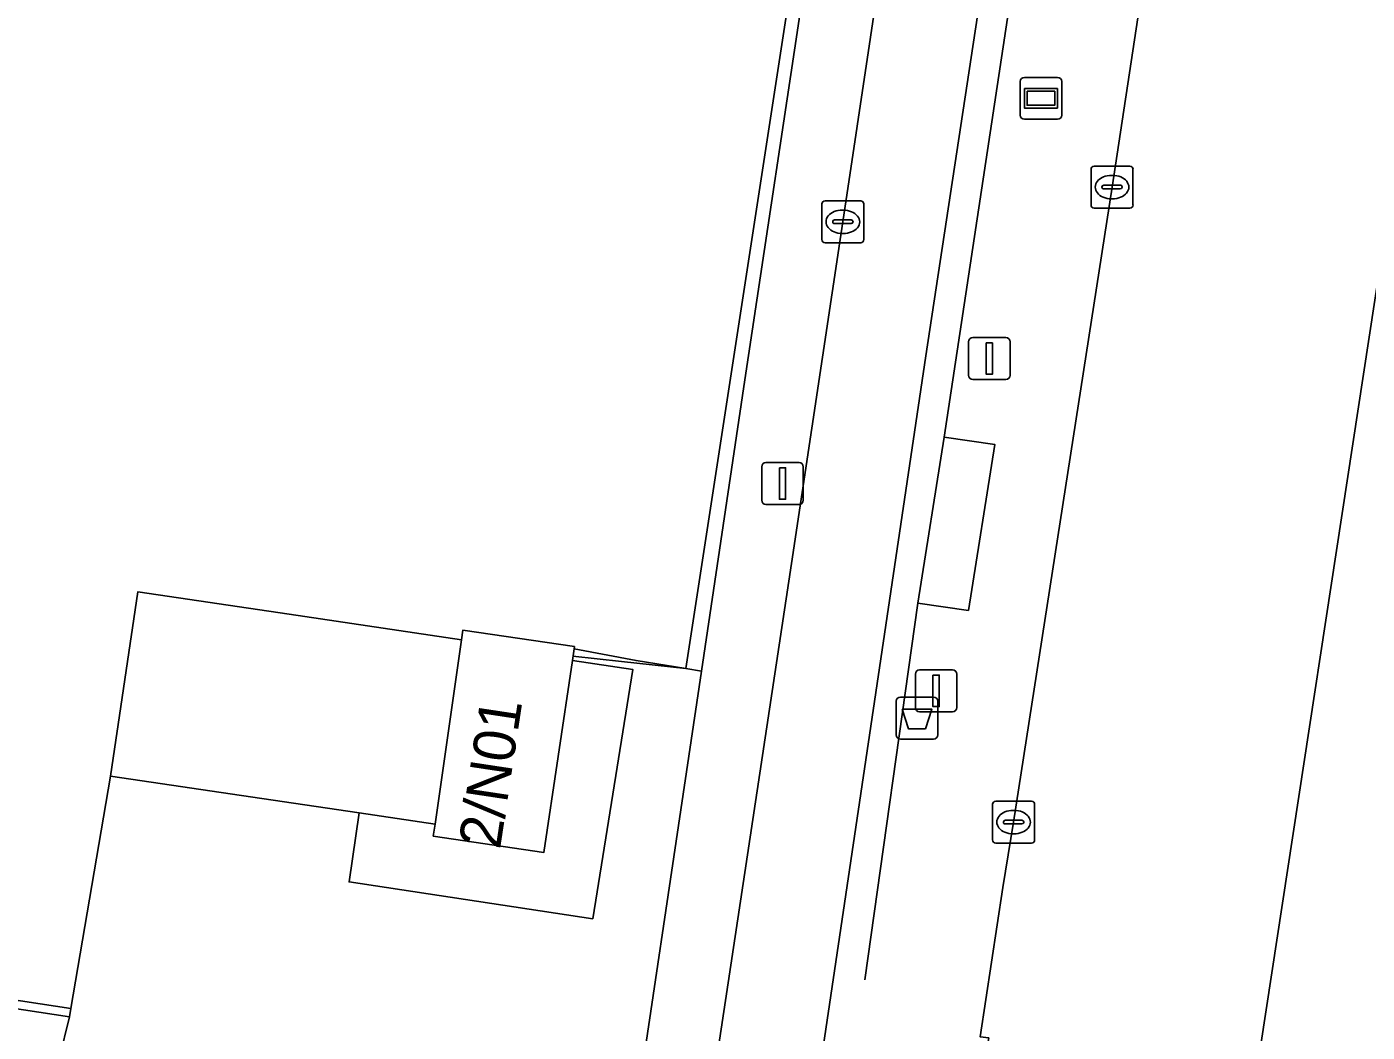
# Model space of a CAD drawing. Extents: x 161090 to 161692, y 379509 to 380907.
# Drawn here: x 161586.23 to 161618.2, y 380444.36 to 380468.34 of the extents above; entities that cross this region are included whole.
import ezdxf

# ---------------------------------------------------------------- set-up
doc = ezdxf.new("R2010")
doc.units = 0
for name, color, linetype in [('IMGEO_Afsluitpaal', 7, 'Continuous'), ('IMGEO_Afvalbak', 7, 'Continuous'), ('IMGEO_Fietspad_gesloten', 7, 'Continuous'), ('IMGEO_Groenvoorziening', 7, 'Continuous'), ('IMGEO_Hek', 7, 'Continuous'), ('IMGEO_Informatiebord', 7, 'Continuous'), ('IMGEO_Kolk', 7, 'Continuous'), ('IMGEO_Lichtmast', 7, 'Continuous'), ('IMGEO_Loofbos', 7, 'Continuous'), ('IMGEO_OVBaan_gesloten', 7, 'Continuous'), ('IMGEO_Pand', 7, 'Continuous'), ('IMGEO_Pand_nummerreeks', 7, 'Continuous'), ('IMGEO_Voetpad_open', 7, 'Continuous')]:
    doc.layers.add(name, color=color, linetype=linetype)

msp = doc.modelspace()

# ---------------------------------------------------------------- linework, layer by layer
at = {"layer": 'IMGEO_Afsluitpaal'}
for p, q in [((161608.694, 380460.028), (161608.694, 380460.828)), ((161608.694, 380460.828), (161608.694, 380460.028)), ((161608.794, 380460.928), (161609.584, 380460.928)), ((161609.584, 380460.928), (161608.794, 380460.928)), ((161609.684, 380460.828), (161609.684, 380460.028)), ((161609.684, 380460.028), (161609.684, 380460.828)), ((161609.584, 380459.928), (161608.794, 380459.928)), ((161608.794, 380459.928), (161609.584, 380459.928)), ((161607.524, 380453.003), (161608.314, 380453.003)), ((161608.314, 380453.003), (161607.524, 380453.003)), ((161607.424, 380452.103), (161607.424, 380452.903)), ((161607.424, 380452.903), (161607.424, 380452.103)), ((161608.414, 380452.903), (161608.414, 380452.103)), ((161608.414, 380452.103), (161608.414, 380452.903)), ((161608.314, 380452.003), (161607.524, 380452.003)), ((161607.524, 380452.003), (161608.314, 380452.003))]:
    msp.add_line(p, q, dxfattribs=at)
for points in [[(161609.114, 380460.803), (161609.264, 380460.803), (161609.264, 380460.053), (161609.114, 380460.053), (161609.114, 380460.803)], [(161607.844, 380452.878), (161607.994, 380452.878), (161607.994, 380452.128), (161607.844, 380452.128), (161607.844, 380452.878)]]:
    msp.add_lwpolyline(points, dxfattribs=at)
for centre, start, end in [((161608.794, 380460.828), 90, 180), ((161608.794, 380460.828), 90, 180), ((161609.584, 380460.828), 0, 90), ((161609.584, 380460.828), 360, 90), ((161608.794, 380460.028), 180, 270), ((161608.794, 380460.028), 180, 270), ((161609.584, 380460.028), 270, 0), ((161609.584, 380460.028), 270, 0), ((161607.524, 380452.903), 90, 180), ((161607.524, 380452.903), 90, 180), ((161608.314, 380452.903), 0, 90), ((161608.314, 380452.903), 360, 90), ((161607.524, 380452.103), 180, 270), ((161607.524, 380452.103), 180, 270), ((161608.314, 380452.103), 270, 0), ((161608.314, 380452.103), 270, 0)]:
    msp.add_arc(centre, 0.1, start, end, dxfattribs=at)
at = {"layer": 'IMGEO_Afvalbak'}
for p, q in [((161607.068, 380452.353), (161607.858, 380452.353)), ((161607.858, 380452.353), (161607.068, 380452.353)), ((161606.968, 380451.453), (161606.968, 380452.253)), ((161606.968, 380452.253), (161606.968, 380451.453)), ((161607.958, 380452.253), (161607.958, 380451.453)), ((161607.958, 380451.453), (161607.958, 380452.253)), ((161607.858, 380451.353), (161607.068, 380451.353)), ((161607.068, 380451.353), (161607.858, 380451.353))]:
    msp.add_line(p, q, dxfattribs=at)
msp.add_lwpolyline([(161607.111, 380452.067), (161607.815, 380452.067), (161607.666, 380451.597), (161607.26, 380451.597), (161607.111, 380452.067)], dxfattribs=at)
for centre, start, end in [((161607.068, 380452.253), 90, 180), ((161607.068, 380452.253), 90, 180), ((161607.858, 380452.253), 0, 90), ((161607.858, 380452.253), 360, 90), ((161607.068, 380451.453), 180, 270), ((161607.068, 380451.453), 180, 270), ((161607.858, 380451.453), 270, 0), ((161607.858, 380451.453), 270, 0)]:
    msp.add_arc(centre, 0.1, start, end, dxfattribs=at)
at = {"layer": 'IMGEO_Fietspad_gesloten'}
for points in [[(161605.166, 380443.632), (161607.677, 380460.497), (161610.329, 380477.98), (161611.098, 380483.56), (161614.581, 380505.893), (161615.743, 380511.514), (161616.298, 380513.769), (161618.457, 380520.726), (161619.94, 380524.783), (161622.539, 380530.803)], [(161612.72, 380509.065), (161611.793, 380503.916), (161610.143, 380493.022), (161609.084, 380485.902), (161608.039, 380479.352), (161605.695, 380463.691), (161604.472, 380455.541), (161602.499, 380442.481), (161602, 380439.232)]]:
    msp.add_lwpolyline(points, dxfattribs=at)
at = {"layer": 'IMGEO_Groenvoorziening'}
for points in [[(161434.436, 380467.982), (161587.251, 380444.727), (161587.284, 380444.922), (161504.1, 380457.592), (161500, 380458.218), (161490.036, 380459.739), (161486.843, 380460.227), (161480.056, 380461.264), (161476.893, 380461.747), (161462.434, 380463.956), (161459.238, 380464.445), (161450.466, 380465.785), (161447.798, 380466.193), (161437.88, 380467.708), (161434.68, 380468.197), (161434.559, 380468.215)], [(161593.917, 380447.944), (161594.16, 380449.59), (161591.835, 380449.934), (161588.227, 380450.468), (161587.284, 380444.922), (161587.251, 380444.727), (161586.511, 380441.722), (161594.765, 380440.636), (161600.379, 380439.897), (161602.323, 380452.975), (161601.946, 380453.038), (161600.762, 380453.225), (161599.284, 380453.506), (161599.243, 380453.228), (161600.682, 380453.015), (161599.729, 380447.067)]]:
    msp.add_lwpolyline(points, close=True, dxfattribs=at)
at = {"layer": 'IMGEO_Hek'}
for points in [[(161599.258, 380453.328), (161600.417, 380453.203), (161601.946, 380453.038), (161608.829, 380497.747), (161609.712, 380502.964)], [(161608.111, 380458.552), (161611.815, 380483.076), (161613.253, 380482.731)], [(161587.251, 380444.727), (161434.436, 380467.982)], [(161607.482, 380454.596), (161606.219, 380445.605)], [(161588.227, 380450.468), (161587.284, 380444.922)], [(161587.284, 380444.922), (161587.251, 380444.727)]]:
    msp.add_lwpolyline(points, dxfattribs=at)
at = {"layer": 'IMGEO_Informatiebord'}
for p, q in [((161610.024, 380467.137), (161610.814, 380467.137)), ((161610.814, 380467.137), (161610.024, 380467.137)), ((161609.924, 380466.237), (161609.924, 380467.037)), ((161609.924, 380467.037), (161609.924, 380466.237)), ((161610.914, 380467.037), (161610.914, 380466.237)), ((161610.914, 380466.237), (161610.914, 380467.037)), ((161610.814, 380466.137), (161610.024, 380466.137)), ((161610.024, 380466.137), (161610.814, 380466.137))]:
    msp.add_line(p, q, dxfattribs=at)
for points in [[(161610.025, 380466.869), (161610.813, 380466.869), (161610.813, 380466.405), (161610.025, 380466.405), (161610.025, 380466.869)], [(161610.09, 380466.804), (161610.09, 380466.47), (161610.748, 380466.47), (161610.748, 380466.804), (161610.09, 380466.804)]]:
    msp.add_lwpolyline(points, dxfattribs=at)
for centre, start, end in [((161610.024, 380467.037), 90, 180), ((161610.024, 380467.037), 90, 180), ((161610.814, 380467.037), 0, 90), ((161610.814, 380467.037), 360, 90), ((161610.024, 380466.237), 180, 270), ((161610.024, 380466.237), 180, 270), ((161610.814, 380466.237), 270, 0), ((161610.814, 380466.237), 270, 0)]:
    msp.add_arc(centre, 0.1, start, end, dxfattribs=at)
at = {"layer": 'IMGEO_Kolk'}
for p, q in [((161611.614, 380464.093), (161611.614, 380464.945)), ((161611.689, 380465.019), (161612.541, 380465.019)), ((161612.615, 380464.945), (161612.615, 380464.093)), ((161611.873, 380464.513), (161611.873, 380464.525)), ((161611.916, 380464.562), (161612.314, 380464.562)), ((161612.102, 380464.799), (161612.127, 380464.799)), ((161612.357, 380464.525), (161612.357, 380464.513)), ((161605.269, 380464.191), (161606.121, 380464.191)), ((161612.311, 380464.476), (161611.913, 380464.476)), ((161612.125, 380464.239), (161612.1, 380464.239)), ((161605.194, 380463.265), (161605.194, 380464.117)), ((161605.682, 380463.971), (161605.707, 380463.971)), ((161606.195, 380464.117), (161606.195, 380463.265)), ((161612.541, 380464.019), (161611.689, 380464.019)), ((161605.453, 380463.685), (161605.453, 380463.697)), ((161605.891, 380463.648), (161605.493, 380463.648)), ((161605.496, 380463.734), (161605.894, 380463.734)), ((161605.937, 380463.697), (161605.937, 380463.685)), ((161605.705, 380463.411), (161605.68, 380463.411)), ((161606.121, 380463.191), (161605.269, 380463.191)), ((161609.267, 380448.945), (161609.267, 380449.797)), ((161609.342, 380449.871), (161610.194, 380449.871)), ((161610.268, 380449.797), (161610.268, 380448.945)), ((161609.755, 380449.651), (161609.78, 380449.651)), ((161609.526, 380449.365), (161609.526, 380449.377)), ((161609.964, 380449.328), (161609.566, 380449.328)), ((161609.569, 380449.414), (161609.967, 380449.414)), ((161610.01, 380449.377), (161610.01, 380449.365)), ((161610.194, 380448.871), (161609.342, 380448.871)), ((161609.778, 380449.091), (161609.753, 380449.091))]:
    msp.add_line(p, q, dxfattribs=at)
for points in [[(161611.614, 380464.093), (161611.614, 380464.945)], [(161611.689, 380465.019), (161612.541, 380465.019)], [(161612.615, 380464.945), (161612.615, 380464.093)], [(161605.269, 380464.191), (161606.121, 380464.191)], [(161605.194, 380463.265), (161605.194, 380464.117)], [(161606.195, 380464.117), (161606.195, 380463.265)], [(161612.541, 380464.019), (161611.689, 380464.019)], [(161606.121, 380463.191), (161605.269, 380463.191)], [(161609.267, 380448.945), (161609.267, 380449.797)], [(161609.342, 380449.871), (161610.194, 380449.871)], [(161610.268, 380449.797), (161610.268, 380448.945)], [(161610.194, 380448.871), (161609.342, 380448.871)]]:
    msp.add_lwpolyline(points, dxfattribs=at)
for centre, radius, start, end in [((161611.691, 380464.943), 0.0765, 91.552, 178.448), ((161611.691, 380464.943), 0.0765, 91.552, 178.448), ((161612.539, 380464.943), 0.0765, 1.552, 88.448), ((161612.539, 380464.943), 0.0765, 1.552, 88.448), ((161611.913, 380464.522), 0.0403, 85.8775, 175.7526), ((161611.91, 380464.512), 0.0366, 178.938, 274.7102), ((161612.314, 380464.519), 0.043, 264.8664, 352.4533), ((161612.318, 380464.524), 0.0386, 1.7309, 96.639), ((161605.271, 380464.115), 0.0765, 91.552, 178.448), ((161605.271, 380464.115), 0.0765, 91.552, 178.448), ((161606.119, 380464.115), 0.0765, 1.552, 88.448), ((161606.119, 380464.115), 0.0765, 1.552, 88.448), ((161611.691, 380464.095), 0.0765, 181.552, 268.448), ((161611.691, 380464.095), 0.0765, 181.552, 268.448), ((161612.539, 380464.095), 0.0765, 271.552, 358.448), ((161612.539, 380464.095), 0.0765, 271.552, 358.448), ((161605.493, 380463.694), 0.0403, 85.8775, 175.7526), ((161605.49, 380463.684), 0.0366, 178.938, 274.7102), ((161605.894, 380463.691), 0.043, 264.8664, 352.4533), ((161605.898, 380463.696), 0.0386, 1.7309, 96.639), ((161605.271, 380463.267), 0.0765, 181.552, 268.448), ((161605.271, 380463.267), 0.0765, 181.552, 268.448), ((161606.119, 380463.267), 0.0765, 271.552, 358.448), ((161606.119, 380463.267), 0.0765, 271.552, 358.448), ((161609.344, 380449.795), 0.0765, 91.552, 178.448), ((161609.344, 380449.795), 0.0765, 91.552, 178.448), ((161610.192, 380449.795), 0.0765, 1.552, 88.448), ((161610.192, 380449.795), 0.0765, 1.552, 88.448), ((161609.566, 380449.374), 0.0403, 85.8775, 175.7526), ((161609.563, 380449.364), 0.0366, 178.938, 274.7102), ((161609.967, 380449.371), 0.043, 264.8664, 352.4533), ((161609.971, 380449.376), 0.0386, 1.7309, 96.639), ((161609.344, 380448.947), 0.0765, 181.552, 268.448), ((161609.344, 380448.947), 0.0765, 181.552, 268.448), ((161610.192, 380448.947), 0.0765, 271.552, 358.448), ((161610.192, 380448.947), 0.0765, 271.552, 358.448)]:
    msp.add_arc(centre, radius, start, end, dxfattribs=at)
for centre, major_axis, ratio, start_param, end_param in [((161612.101, 380464.519), (-0.387, 0.002), 0.722429, 4.712389, 7.853982), ((161612.126, 380464.519), (-0.39, 0.002), 0.717154, 1.570796, 4.712389), ((161605.681, 380463.691), (-0.387, 0.002), 0.722429, 4.712389, 7.853982), ((161605.706, 380463.691), (-0.39, 0.002), 0.717154, 1.570796, 4.712389), ((161609.754, 380449.371), (-0.387, 0.002), 0.722429, 4.712389, 7.853982), ((161609.779, 380449.371), (-0.39, 0.002), 0.717154, 1.570796, 4.712389)]:
    msp.add_ellipse(centre, major_axis=major_axis, ratio=ratio, start_param=start_param, end_param=end_param, dxfattribs=at)
at = {"layer": 'IMGEO_Lichtmast'}
for p, q in [((161603.76, 380457.047), (161603.76, 380457.847)), ((161603.76, 380457.847), (161603.76, 380457.047)), ((161603.86, 380457.947), (161604.65, 380457.947)), ((161604.65, 380457.947), (161603.86, 380457.947)), ((161604.75, 380457.847), (161604.75, 380457.047)), ((161604.75, 380457.047), (161604.75, 380457.847)), ((161604.65, 380456.947), (161603.86, 380456.947)), ((161603.86, 380456.947), (161604.65, 380456.947))]:
    msp.add_line(p, q, dxfattribs=at)
msp.add_lwpolyline([(161604.18, 380457.822), (161604.33, 380457.822), (161604.33, 380457.072), (161604.18, 380457.072), (161604.18, 380457.822)], dxfattribs=at)
for centre, start, end in [((161603.86, 380457.847), 90, 180), ((161603.86, 380457.847), 90, 180), ((161604.65, 380457.847), 0, 90), ((161604.65, 380457.847), 360, 90), ((161603.86, 380457.047), 180, 270), ((161603.86, 380457.047), 180, 270), ((161604.65, 380457.047), 270, 0), ((161604.65, 380457.047), 270, 0)]:
    msp.add_arc(centre, 0.1, start, end, dxfattribs=at)
at = {"layer": 'IMGEO_Loofbos'}
for points in [[(161450.466, 380465.785), (161459.238, 380464.445), (161462.434, 380463.956), (161476.893, 380461.747), (161480.056, 380461.264), (161486.843, 380460.227), (161490.036, 380459.739), (161500, 380458.218), (161504.1, 380457.592), (161587.284, 380444.922), (161588.227, 380450.468), (161588.877, 380454.862), (161592.486, 380454.328), (161596.599, 380453.72), (161596.632, 380453.952), (161599.292, 380453.559), (161599.284, 380453.506), (161600.762, 380453.225), (161601.946, 380453.038), (161602.323, 380452.975), (161603.356, 380459.92), (161606.301, 380479.461), (161609.342, 380499.396)], [(161435.157, 380462.917), (161501.097, 380452.867), (161512.062, 380451.442), (161512, 380451.031), (161556.757, 380444.287), (161581.527, 380440.544), (161585.979, 380439.898), (161586.07, 380439.832), (161586.237, 380439.711), (161586.511, 380441.722), (161587.251, 380444.727), (161434.436, 380467.982)]]:
    msp.add_lwpolyline(points, dxfattribs=at)
at = {"layer": 'IMGEO_OVBaan_gesloten'}
for points in [[(161612.306, 380425.991), (161612.632, 380427.317), (161613.369, 380430.195), (161613.938, 380434.18), (161614.833, 380438.994), (161615.534, 380443.23), (161620.823, 380477.775), (161621.459, 380481.861), (161623.867, 380497.327), (161624.115, 380498.972), (161624.812, 380502.834), (161625.926, 380508.173), (161627.09, 380513.518), (161628.06, 380517.418), (161629.127, 380521.326), (161630.548, 380526.14), (161631.755, 380529.867), (161633.706, 380535.575), (161635.012, 380539.309), (161636.298, 380542.203), (161639.063, 380548.6), (161641.573, 380554.027), (161648.889, 380569.692), (161650.916, 380575.021)], [(161625.456, 380531.961), (161623.962, 380527.195), (161622.492, 380522.18), (161621.348, 380518.104), (161620.856, 380516.203), (161620.382, 380514.25), (161618.941, 380507.408), (161618.209, 380503.248), (161614.938, 380482.977), (161614.315, 380478.892), (161614.112, 380477.696), (161612.115, 380464.519), (161609.768, 380449.371), (161609.513, 380447.808), (161608.972, 380444.245), (161609.174, 380444.224), (161607.461, 380434.986), (161606.403, 380431.194), (161606.173, 380430.34), (161605.644, 380428.381), (161605.26, 380427.021), (161603.537, 380421.449)]]:
    msp.add_lwpolyline(points, dxfattribs=at)
at = {"layer": 'IMGEO_Pand'}
for points in [[(161596.599, 380453.72), (161592.486, 380454.328), (161588.877, 380454.862), (161588.227, 380450.468), (161591.835, 380449.934), (161594.16, 380449.59), (161595.968, 380449.323)], [(161599.243, 380453.228), (161599.284, 380453.506), (161599.292, 380453.559), (161596.632, 380453.952), (161596.599, 380453.72), (161595.968, 380449.323), (161595.926, 380449.037), (161598.566, 380448.646)]]:
    msp.add_lwpolyline(points, close=True, dxfattribs=at)
at = {"layer": 'IMGEO_Voetpad_open'}
for points in [[(161602, 380439.232), (161602.499, 380442.481), (161604.472, 380455.541), (161605.695, 380463.691), (161608.039, 380479.352), (161609.084, 380485.902), (161610.143, 380493.022), (161611.793, 380503.916), (161612.72, 380509.065)], [(161609.91, 380502.936), (161609.342, 380499.396), (161606.301, 380479.461), (161603.356, 380459.92), (161602.323, 380452.975), (161600.379, 380439.897), (161594.765, 380440.636), (161586.511, 380441.722), (161586.237, 380439.711), (161591.165, 380438.958), (161592.467, 380437.288), (161598.584, 380436.474)], [(161614.938, 380482.977), (161611.098, 380483.56), (161610.329, 380477.98), (161607.677, 380460.497), (161605.166, 380443.632)], [(161605.679, 380435.339), (161607.461, 380434.986), (161609.174, 380444.224), (161608.972, 380444.245), (161609.513, 380447.808), (161609.768, 380449.371), (161612.115, 380464.519), (161614.112, 380477.696), (161614.315, 380478.892), (161614.938, 380482.977)], [(161625.936, 380463.932), (161625.863, 380463.505), (161622.81, 380463.989), (161625.215, 380478.879), (161625.57, 380481.218), (161621.459, 380481.861), (161620.823, 380477.775), (161615.534, 380443.23), (161614.833, 380438.994), (161613.938, 380434.18), (161620.113, 380433.098)]]:
    msp.add_lwpolyline(points, dxfattribs=at)
for points in [[(161607.482, 380454.596), (161608.111, 380458.552), (161609.32, 380458.375), (161608.691, 380454.419)], [(161607.482, 380454.596), (161608.691, 380454.419), (161609.32, 380458.375), (161608.111, 380458.552)], [(161599.243, 380453.228), (161598.566, 380448.646), (161595.926, 380449.037), (161595.968, 380449.323), (161594.16, 380449.59), (161593.917, 380447.944), (161599.729, 380447.067), (161600.682, 380453.015)]]:
    msp.add_lwpolyline(points, close=True, dxfattribs=at)

# ---------------------------------------------------------------- texts
at = {"layer": 'IMGEO_Pand_nummerreeks'}
msp.add_text('2/N01', height=1, rotation=81.4058, dxfattribs=at).set_placement((161597.516, 380448.701))

doc.saveas('drawing.dxf')
